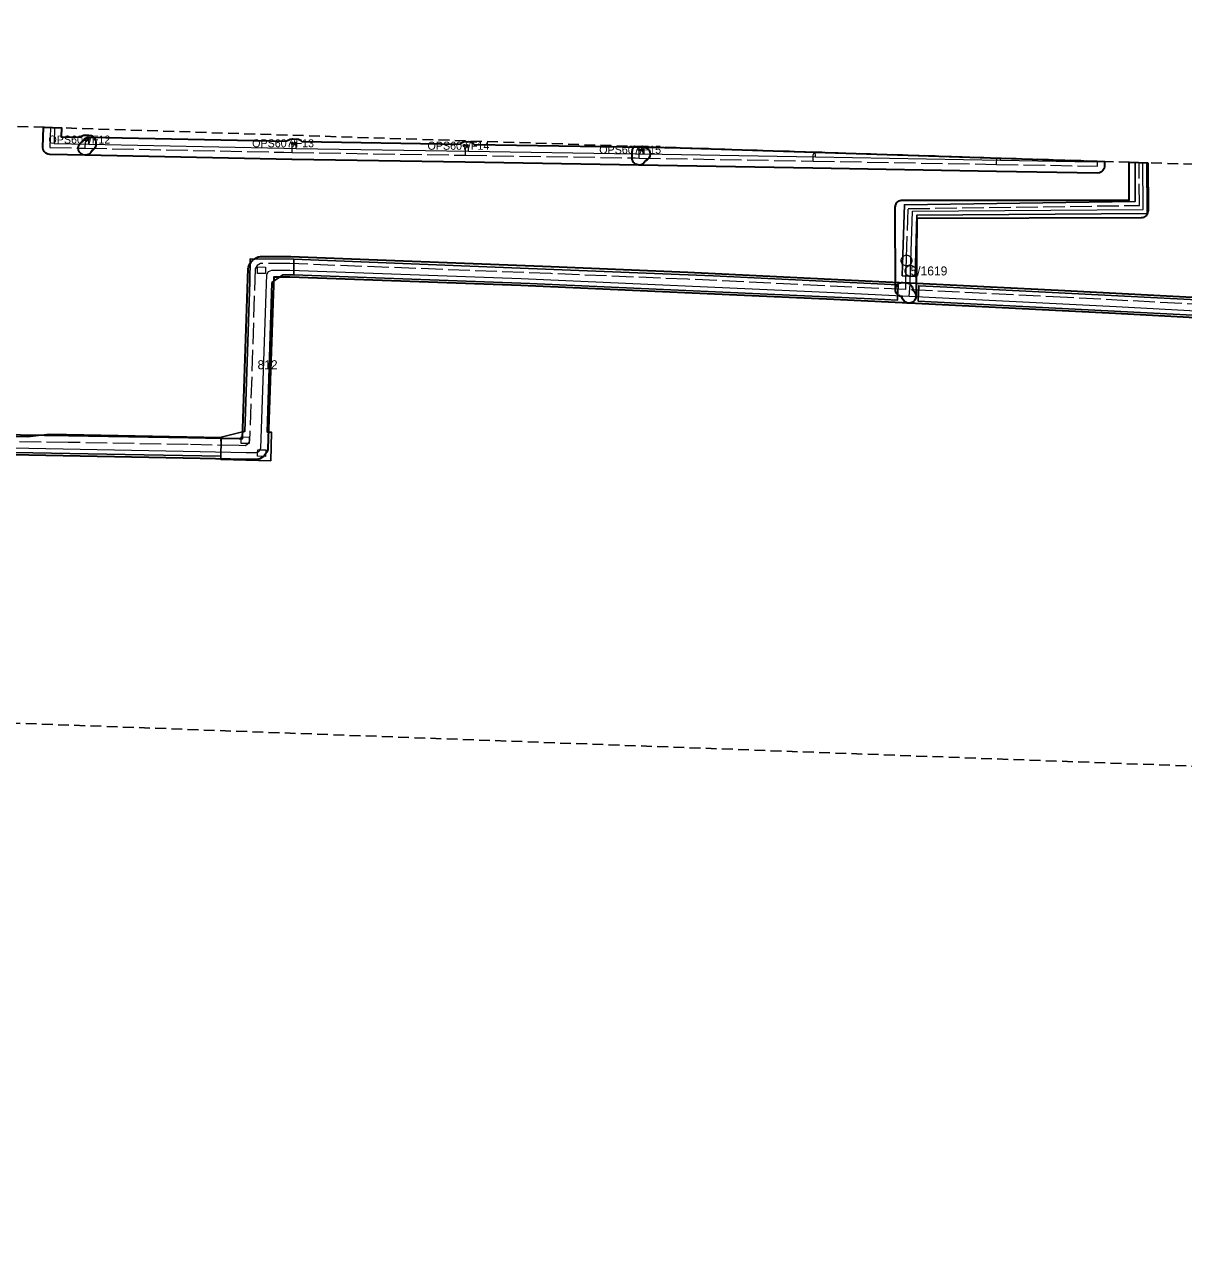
# Model space of a CAD drawing. Extents: x -451331 to -449998, y -1101254 to -1101132.
# Drawn here: x -451012.5 to -450896.6, y -1101253.5 to -1101132.1 of the extents above; entities that cross this region are included whole.
import ezdxf

# ---------------------------------------------------------------- set-up
doc = ezdxf.new("R2010")
doc.units = 0
doc.header["$LTSCALE"] = 0.36
doc.header["$PDMODE"] = 32
doc.header["$PDSIZE"] = 0.18
doc.linetypes.add('LONG_DASHED', pattern=[7.5, 6, -1.5])
doc.linetypes.add('MEDIUM_DASHED', pattern=[4.5, 3, -1.5])
for name, color, linetype, lineweight in [('2', 7, 'Continuous', 13), ('3', 7, 'Continuous', 25), ('62', 7, 'MEDIUM_DASHED', 25), ('8', 7, 'Continuous', 35)]:
    doc.layers.add(name, color=color, linetype=linetype, lineweight=lineweight)
doc.layers.add('4', color=7, linetype='Continuous')
doc.layers.add('7', color=7, linetype='Continuous')

msp = doc.modelspace()

# ---------------------------------------------------------------- linework, layer by layer
at = {"layer": '2', "linetype": 'LONG_DASHED'}
for p, q in [((-451006.417, -1101144.484), (-451006.398, -1101143.853)), ((-451006.417, -1101144.484), (-450986.553, -1101144.893)), ((-451006.398, -1101143.853), (-451006.098, -1101143.622)), ((-450985.717, -1101144.241), (-450985.733, -1101143.991)), ((-450985.729, -1101144.91), (-450985.717, -1101144.241)), ((-450968.417, -1101145.188), (-450968.399, -1101144.517)), ((-450968.399, -1101144.517), (-450968.2, -1101144.241)), ((-450951.027, -1101144.855), (-450951.034, -1101144.636)), ((-450986.553, -1101144.893), (-450985.729, -1101144.91)), ((-450985.729, -1101144.91), (-450968.417, -1101145.188)), ((-450968.417, -1101145.188), (-450951.418, -1101145.461)), ((-450951.418, -1101145.461), (-450951.052, -1101145.467)), ((-450951.052, -1101145.467), (-450951.027, -1101144.855)), ((-450933.653, -1101145.776), (-450915.303, -1101146.1)), ((-450933.645, -1101145.136), (-450933.495, -1101144.872)), ((-450915.303, -1101146.1), (-450915.287, -1101145.458))]:
    msp.add_line(p, q, dxfattribs=at)
at = {"layer": '2'}
for p, q in [((-451006.053, -1101143.886), (-451006.098, -1101143.622)), ((-451006.053, -1101144.092), (-451006.053, -1101143.886)), ((-451006.053, -1101144.092), (-450986.56, -1101144.491)), ((-450986.56, -1101144.491), (-450985.343, -1101144.515)), ((-450985.331, -1101144.243), (-450985.733, -1101143.991)), ((-450985.343, -1101144.515), (-450985.331, -1101144.243)), ((-450985.343, -1101144.515), (-450968.107, -1101144.793)), ((-450968.108, -1101144.522), (-450968.2, -1101144.241)), ((-450968.107, -1101144.793), (-450968.108, -1101144.522)), ((-450950.623, -1101144.848), (-450951.034, -1101144.636)), ((-450968.107, -1101144.793), (-450951.414, -1101145.062)), ((-450951.414, -1101145.062), (-450950.626, -1101145.074)), ((-450950.626, -1101145.074), (-450950.623, -1101144.848)), ((-450933.406, -1101145.379), (-450950.626, -1101145.074)), ((-450933.403, -1101145.162), (-450933.461, -1101144.873)), ((-450933.406, -1101145.379), (-450933.403, -1101145.162)), ((-450914.902, -1101145.708), (-450933.406, -1101145.379)), ((-450914.902, -1101145.708), (-450914.898, -1101145.471))]:
    msp.add_line(p, q, dxfattribs=at)
at = {"layer": '2', "linetype": 'LONG_DASHED'}
for points in [[(-451009.905, -1101142.414), (-451009.946, -1101144.421), (-451006.417, -1101144.484)], [(-450951.052, -1101145.467), (-450933.653, -1101145.776), (-450933.645, -1101145.136)], [(-450915.303, -1101146.1), (-450905.222, -1101146.278), (-450905.207, -1101145.783)], [(-450924.298, -1101155.424), (-450924.146, -1101150.53), (-450901.027, -1101150.203), (-450901.058, -1101145.916)], [(-450924.388, -1101158.628), (-450924.366, -1101157.596), (-450924.336, -1101156.646), (-450924.298, -1101155.424)], [(-450985.95, -1101156.019), (-450988.905, -1101156.019), (-450989.219, -1101156.199), (-450989.429, -1101156.538), (-450989.989, -1101173.782), (-450990.166, -1101174.083), (-450990.445, -1101174.229), (-450991.036, -1101174.218)], [(-450924.388, -1101158.628), (-450946.22, -1101157.585), (-450959.868, -1101157.026), (-450985.95, -1101156.023)], [(-450886.009, -1101160.581), (-450908.217, -1101159.417), (-450924.388, -1101158.628)], [(-450991.036, -1101174.218), (-450996.119, -1101174.12), (-451008.119, -1101173.899), (-451020.119, -1101173.739)]]:
    msp.add_lwpolyline(points, dxfattribs=at)
at = {"layer": '2'}
for points in [[(-451009.506, -1101142.426), (-451009.538, -1101144.03), (-451006.053, -1101144.092)], [(-450905.608, -1101145.77), (-450905.611, -1101145.872), (-450914.902, -1101145.708)], [(-450923.901, -1101156.581), (-450923.875, -1101155.812), (-450923.703, -1101150.788), (-450900.651, -1101150.627), (-450900.682, -1101145.928)], [(-450990.341, -1101174.899), (-450989.32, -1101174.919), (-450989.039, -1101174.76), (-450988.859, -1101174.483), (-450988.358, -1101159.964), (-450988.26, -1101157.121), (-450988.093, -1101156.826), (-450987.772, -1101156.67), (-450985.95, -1101156.67)], [(-450985.95, -1101156.67), (-450962.85, -1101157.511), (-450931.54, -1101158.896), (-450924.057, -1101159.279)], [(-450924.057, -1101159.279), (-450923.953, -1101158.105), (-450923.901, -1101156.581)], [(-450924.057, -1101159.279), (-450903.363, -1101160.303), (-450881.853, -1101161.467), (-450860.382, -1101162.6), (-450860.033, -1101162.303), (-450860.078, -1101159.959), (-450859.628, -1101159.641), (-450858.305, -1101159.721), (-450857.961, -1101160.144), (-450858.14, -1101162.461), (-450857.872, -1101162.774), (-450818.326, -1101166.124), (-450811.077, -1101166.864), (-450792.45, -1101169.087), (-450763.663, -1101172.871), (-450762.79, -1101172.897), (-450762.34, -1101172.685), (-450762.092, -1101170.332), (-450761.805, -1101169.929), (-450760.353, -1101170.217), (-450760.111, -1101170.64), (-450760.277, -1101172.871), (-450760.195, -1101173.307), (-450753.15, -1101174.471)], [(-451018.92, -1101174.35), (-451006.92, -1101174.589), (-450994.929, -1101174.809), (-450990.341, -1101174.899)]]:
    msp.add_lwpolyline(points, dxfattribs=at)
at = {"layer": '3'}
for points in [[(-450924.748, -1101157.241), (-450924.688, -1101155.099), (-450924.518, -1101150.135), (-450901.434, -1101149.809), (-450901.462, -1101145.903), (-450900.286, -1101145.941), (-450900.248, -1101151.024), (-450923.28, -1101151.185), (-450923.459, -1101157.305)], [(-450987.759, -1101157.91), (-450988.242, -1101172.873), (-450987.789, -1101172.886), (-450987.881, -1101175.73), (-450992.858, -1101175.622), (-450992.816, -1101173.388), (-450990.554, -1101172.806), (-450990.451, -1101172.809), (-450989.961, -1101157.841), (-450989.961, -1101157.838), (-450989.926, -1101155.537), (-450985.552, -1101155.582), (-450985.566, -1101157.158), (-450986.659, -1101157.14)], [(-450925.133, -1101158.145), (-450925.198, -1101159.67), (-450927.794, -1101159.538), (-450961.967, -1101158), (-450985.564, -1101157.134), (-450985.552, -1101155.588), (-450943.644, -1101157.258)], [(-451031.478, -1101178.392), (-451031.501, -1101179.236), (-451038.169, -1101179.216), (-451038.153, -1101178.327), (-451038.111, -1101174.703), (-451060.154, -1101174.434), (-451060.114, -1101172.594), (-451035.097, -1101172.968), (-451013.743, -1101173.315), (-451012.161, -1101173.348), (-451009.999, -1101173.067), (-450992.816, -1101173.411), (-450992.865, -1101173.754), (-450992.823, -1101173.755), (-450992.851, -1101175.262), (-451002.429, -1101175.114), (-451013.496, -1101174.908), (-451031.383, -1101174.657)]]:
    msp.add_lwpolyline(points, close=True, dxfattribs=at)
at = {"layer": '3', "lineweight": 13}
for points in [[(-450924.307, -1101155.172), (-450924.213, -1101155.18), (-450924.122, -1101155.205), (-450924.036, -1101155.245), (-450923.958, -1101155.299), (-450923.891, -1101155.366), (-450923.837, -1101155.444), (-450923.797, -1101155.53), (-450923.773, -1101155.621), (-450923.764, -1101155.715), (-450923.773, -1101155.809), (-450923.797, -1101155.901), (-450923.837, -1101155.987), (-450923.891, -1101156.064), (-450923.958, -1101156.131), (-450924.036, -1101156.186), (-450924.122, -1101156.225), (-450924.213, -1101156.25), (-450924.307, -1101156.258), (-450924.402, -1101156.25), (-450924.493, -1101156.225), (-450924.579, -1101156.186), (-450924.656, -1101156.131), (-450924.723, -1101156.064), (-450924.778, -1101155.987), (-450924.818, -1101155.901), (-450924.842, -1101155.809), (-450924.85, -1101155.715), (-450924.842, -1101155.621), (-450924.818, -1101155.53), (-450924.778, -1101155.444), (-450924.723, -1101155.366), (-450924.656, -1101155.299), (-450924.579, -1101155.245), (-450924.493, -1101155.205), (-450924.402, -1101155.18)], [(-450989.183, -1101156.344), (-450988.386, -1101156.364), (-450988.402, -1101157.019), (-450989.199, -1101157)], [(-450923.907, -1101156.211), (-450923.813, -1101156.219), (-450923.721, -1101156.243), (-450923.635, -1101156.283), (-450923.558, -1101156.338), (-450923.491, -1101156.405), (-450923.437, -1101156.482), (-450923.397, -1101156.568), (-450923.372, -1101156.659), (-450923.364, -1101156.754), (-450923.372, -1101156.848), (-450923.397, -1101156.939), (-450923.437, -1101157.025), (-450923.491, -1101157.103), (-450923.558, -1101157.17), (-450923.635, -1101157.224), (-450923.721, -1101157.264), (-450923.813, -1101157.289), (-450923.907, -1101157.297), (-450924.001, -1101157.289), (-450924.093, -1101157.264), (-450924.178, -1101157.224), (-450924.256, -1101157.17), (-450924.323, -1101157.103), (-450924.377, -1101157.025), (-450924.417, -1101156.939), (-450924.442, -1101156.848), (-450924.45, -1101156.754), (-450924.442, -1101156.659), (-450924.417, -1101156.568), (-450924.377, -1101156.482), (-450924.323, -1101156.405), (-450924.256, -1101156.338), (-450924.178, -1101156.283), (-450924.093, -1101156.243), (-450924.001, -1101156.219)], [(-450990.815, -1101173.347), (-450990.018, -1101173.366), (-450990.034, -1101174.022), (-450990.831, -1101174.002)], [(-450989.169, -1101174.634), (-450988.373, -1101174.653), (-450988.389, -1101175.308), (-450989.185, -1101175.289)]]:
    msp.add_lwpolyline(points, close=True, dxfattribs=at)
at = {"layer": '3'}
msp.add_lwpolyline([(-450895.688, -1101161.169), (-450923.154, -1101159.774), (-450923.082, -1101158.243), (-450920.932, -1101158.346), (-450889.362, -1101159.955)], dxfattribs=at)
at = {"layer": '4'}
for p in [(-451006.099, -1101143.621), (-450985.733, -1101143.992), (-450968.2, -1101144.24), (-450951.033, -1101144.635)]:
    msp.add_point(p, dxfattribs=at)
at = {"layer": '62'}
msp.add_lwpolyline([(-450786.261, -1101210.25), (-451322.174, -1101190.711), (-451330.547, -1101132.096), (-450766.722, -1101150.239), (-450459.689, -1101190.711), (-449997.743, -1101194.898), (-449997.743, -1101249.327), (-450456.897, -1101253.514)], close=True, dxfattribs=at)
at = {"layer": '7'}
for p in [(-451006.437, -1101143.607), (-451006.099, -1101143.621), (-450985.733, -1101143.992), (-450985.395, -1101144.006), (-450968.538, -1101144.225), (-450968.2, -1101144.24), (-450951.033, -1101144.635), (-450950.696, -1101144.65)]:
    msp.add_point(p, dxfattribs=at)
at = {"layer": '8'}
for points in [[(-451005.809, -1101144.813), (-451005.859, -1101144.906), (-451005.862, -1101144.909), (-451005.865, -1101144.914), (-451005.941, -1101144.985), (-451006.016, -1101145.058), (-451006.021, -1101145.06), (-451006.024, -1101145.063), (-451006.119, -1101145.108), (-451006.213, -1101145.154), (-451006.218, -1101145.155), (-451006.222, -1101145.157), (-451006.326, -1101145.17), (-451006.43, -1101145.184), (-451009.959, -1101145.121), (-451010.175, -1101145.083), (-451010.369, -1101144.98), (-451010.521, -1101144.822), (-451010.616, -1101144.625), (-451010.646, -1101144.407), (-451010.605, -1101142.391), (-451008.806, -1101142.449), (-451008.824, -1101143.342), (-451006.9, -1101143.376), (-451006.791, -1101143.274), (-451006.593, -1101143.18), (-451006.375, -1101143.153), (-451006.16, -1101143.194), (-451006.147, -1101143.201), (-451006.057, -1101143.186), (-451005.84, -1101143.22), (-451005.645, -1101143.318), (-451005.489, -1101143.472), (-451005.389, -1101143.667), (-451005.354, -1101143.883), (-451005.353, -1101144.088), (-451005.354, -1101144.096), (-451005.353, -1101144.104), (-451005.37, -1101144.204), (-451005.386, -1101144.305), (-451005.389, -1101144.312), (-451005.391, -1101144.32), (-451005.439, -1101144.409), (-451005.484, -1101144.5), (-451005.49, -1101144.506), (-451005.494, -1101144.513), (-451005.567, -1101144.584), (-451005.638, -1101144.656), (-451005.645, -1101144.66), (-451005.651, -1101144.665), (-451005.743, -1101144.71), (-451005.758, -1101144.718), (-451005.759, -1101144.722)], [(-450984.777, -1101143.824), (-450968.942, -1101144.079), (-450968.796, -1101143.941), (-450968.599, -1101143.846), (-450968.382, -1101143.818), (-450968.244, -1101143.843), (-450968.114, -1101143.822), (-450967.897, -1101143.854), (-450967.701, -1101143.952), (-450967.55, -1101144.101), (-450950.615, -1101144.375), (-450950.399, -1101144.412), (-450950.206, -1101144.515), (-450950.054, -1101144.672), (-450949.957, -1101144.869), (-450949.927, -1101145.086), (-450949.964, -1101145.302), (-450950.067, -1101145.495), (-450950.224, -1101145.647), (-450950.414, -1101145.74), (-450950.492, -1101145.887), (-450950.649, -1101146.039), (-450950.846, -1101146.136), (-450951.063, -1101146.166), (-450968.428, -1101145.887), (-450985.741, -1101145.609), (-450985.742, -1101145.609), (-450985.743, -1101145.609), (-450985.744, -1101145.609), (-450985.744, -1101145.609), (-451006.432, -1101145.184), (-451006.647, -1101145.146), (-451006.84, -1101145.042), (-451006.992, -1101144.884), (-451007.087, -1101144.687), (-451007.117, -1101144.47), (-451007.079, -1101144.255), (-451006.975, -1101144.061), (-451006.817, -1101143.91), (-451006.712, -1101143.859), (-451006.61, -1101143.668), (-451006.452, -1101143.517), (-451006.255, -1101143.421), (-451006.038, -1101143.392), (-450986.252, -1101143.797), (-450986.117, -1101143.666), (-450985.92, -1101143.571), (-450985.703, -1101143.541), (-450985.524, -1101143.572), (-450985.515, -1101143.568), (-450985.297, -1101143.544), (-450985.083, -1101143.589), (-450984.892, -1101143.697)], [(-450951.071, -1101146.165), (-450951.079, -1101146.166), (-450951.179, -1101146.146), (-450951.28, -1101146.128), (-450951.286, -1101146.125), (-450951.294, -1101146.123), (-450951.383, -1101146.073), (-450951.473, -1101146.025), (-450951.478, -1101146.02), (-450951.485, -1101146.016), (-450951.554, -1101145.941), (-450951.625, -1101145.868), (-450951.628, -1101145.861), (-450951.634, -1101145.855), (-450951.676, -1101145.763), (-450951.721, -1101145.671), (-450951.722, -1101145.663), (-450951.725, -1101145.657), (-450951.737, -1101145.555), (-450951.751, -1101145.454), (-450951.75, -1101145.447), (-450951.751, -1101145.439), (-450951.728, -1101144.841), (-450951.728, -1101144.833), (-450951.693, -1101144.616), (-450951.594, -1101144.421), (-450951.467, -1101144.294), (-450950.155, -1101144.336), (-450950.109, -1101144.383), (-450946.939, -1101144.44), (-450904.508, -1101145.805), (-450904.523, -1101146.3), (-450904.563, -1101146.513), (-450904.667, -1101146.704), (-450904.824, -1101146.854), (-450905.02, -1101146.949), (-450905.235, -1101146.978), (-450915.316, -1101146.799), (-450933.666, -1101146.475), (-450951.064, -1101146.166)], [(-450900.173, -1101145.945), (-450900.165, -1101150.754), (-450900.175, -1101150.876), (-450900.207, -1101150.993), (-450900.258, -1101151.104), (-450900.328, -1101151.204), (-450900.414, -1101151.29), (-450900.514, -1101151.36), (-450900.624, -1101151.412), (-450900.742, -1101151.444), (-450900.863, -1101151.455), (-450923.275, -1101151.502), (-450923.357, -1101159.286), (-450923.369, -1101159.405), (-450923.401, -1101159.521), (-450923.452, -1101159.629), (-450923.52, -1101159.728), (-450923.605, -1101159.813), (-450923.702, -1101159.882), (-450923.81, -1101159.934), (-450923.926, -1101159.966), (-450924.045, -1101159.979), (-450924.165, -1101159.97), (-450924.281, -1101159.942), (-450924.391, -1101159.894), (-450924.491, -1101159.828), (-450924.578, -1101159.746), (-450924.651, -1101159.651), (-450924.705, -1101159.544), (-450924.741, -1101159.43), (-450924.757, -1101159.311), (-450924.874, -1101159.296), (-450924.987, -1101159.261), (-450925.093, -1101159.207), (-450925.188, -1101159.136), (-450925.27, -1101159.051), (-450925.336, -1101158.953), (-450925.385, -1101158.845), (-450925.415, -1101158.73), (-450925.425, -1101158.612), (-450925.432, -1101150.374), (-450925.424, -1101150.264), (-450925.398, -1101150.157), (-450925.356, -1101150.056), (-450925.299, -1101149.962), (-450925.227, -1101149.878), (-450925.144, -1101149.807), (-450925.05, -1101149.749), (-450924.948, -1101149.707), (-450924.841, -1101149.682), (-450924.732, -1101149.673), (-450902.038, -1101149.693), (-450902.038, -1101145.885)]]:
    msp.add_lwpolyline(points, close=True, dxfattribs=at)
for points in [[(-451020.111, -1101173.04), (-451008.108, -1101173.2), (-450996.106, -1101173.42), (-450991.022, -1101173.518), (-450990.681, -1101173.525), (-450990.128, -1101156.515), (-450990.114, -1101156.395), (-450990.079, -1101156.279), (-450990.024, -1101156.17), (-450989.815, -1101155.832), (-450989.746, -1101155.738), (-450989.663, -1101155.658), (-450989.567, -1101155.592), (-450989.253, -1101155.412), (-450989.143, -1101155.361), (-450989.026, -1101155.33), (-450988.905, -1101155.32), (-450985.95, -1101155.32), (-450985.85, -1101155.327), (-450959.84, -1101156.327), (-450946.189, -1101156.886)], [(-450946.189, -1101156.886), (-450924.355, -1101157.929), (-450924.244, -1101157.943), (-450924.137, -1101157.975), (-450924.036, -1101158.023), (-450923.944, -1101158.087), (-450923.863, -1101158.165), (-450923.796, -1101158.254), (-450923.744, -1101158.354), (-450923.709, -1101158.46), (-450923.691, -1101158.57), (-450923.69, -1101158.682), (-450923.596, -1101158.752), (-450923.515, -1101158.836), (-450923.449, -1101158.932), (-450923.399, -1101159.039), (-450923.369, -1101159.152), (-450923.357, -1101159.268), (-450923.365, -1101159.385), (-450923.392, -1101159.499), (-450923.438, -1101159.606), (-450923.502, -1101159.705), (-450923.58, -1101159.791), (-450923.673, -1101159.864), (-450923.775, -1101159.92), (-450923.886, -1101159.958), (-450924.001, -1101159.977), (-450924.076, -1101159.978), (-450924.093, -1101159.978), (-450931.573, -1101159.595), (-450962.879, -1101158.21), (-450985.95, -1101157.37), (-450985.975, -1101157.369), (-450987.568, -1101157.37), (-450987.658, -1101159.989), (-450988.159, -1101174.508), (-450988.169, -1101174.602), (-450988.192, -1101174.695), (-450988.226, -1101174.784), (-450988.273, -1101174.867), (-450988.454, -1101175.143), (-450988.521, -1101175.23), (-450988.602, -1101175.306), (-450988.693, -1101175.368), (-450988.974, -1101175.528), (-450989.058, -1101175.568), (-450989.148, -1101175.598), (-450989.24, -1101175.615), (-450989.334, -1101175.619), (-450990.355, -1101175.599), (-450990.357, -1101175.599), (-450994.943, -1101175.509), (-451006.933, -1101175.289), (-451018.931, -1101175.049)], [(-450881.89, -1101162.166), (-450903.4, -1101161.002), (-450924.092, -1101159.978), (-450924.205, -1101159.962), (-450924.313, -1101159.928), (-450924.415, -1101159.876), (-450924.507, -1101159.809), (-450924.586, -1101159.728), (-450924.652, -1101159.635), (-450924.702, -1101159.533), (-450924.734, -1101159.424), (-450924.749, -1101159.311), (-450924.759, -1101159.311), (-450924.874, -1101159.296), (-450924.985, -1101159.262), (-450925.088, -1101159.21), (-450925.182, -1101159.142), (-450925.263, -1101159.06), (-450925.329, -1101158.965), (-450925.379, -1101158.861), (-450925.412, -1101158.75), (-450925.425, -1101158.635), (-450925.419, -1101158.52), (-450925.395, -1101158.407), (-450925.352, -1101158.299), (-450925.292, -1101158.2), (-450925.217, -1101158.113), (-450925.128, -1101158.039), (-450925.028, -1101157.98), (-450924.92, -1101157.939), (-450924.807, -1101157.916), (-450924.691, -1101157.912), (-450908.487, -1101158.702), (-450886.233, -1101159.866)]]:
    msp.add_lwpolyline(points, dxfattribs=at)

# ---------------------------------------------------------------- texts
at = {"layer": '3'}
for s, p in [('5/1619 ', (-450923.907, -1101157.203)), ('812 ', (-450989.194, -1101166.585))]:
    msp.add_text(s, height=0.9, dxfattribs=at).set_placement(p)
at = {"layer": '4'}
for s, p in [('OPS607/F12', (-451010.099, -1101144.021)), ('OPS607/F13', (-450989.733, -1101144.392)), ('OPS607/F14', (-450972.2, -1101144.64)), ('OPS607/F15', (-450955.033, -1101145.035))]:
    msp.add_text(s, height=0.8, dxfattribs=at).set_placement(p)

doc.saveas('drawing.dxf')
